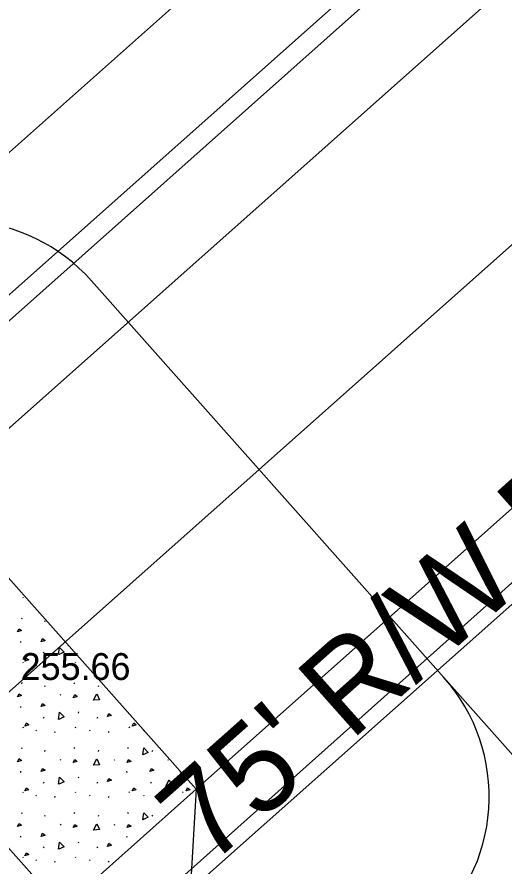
# Model space of a CAD drawing. Extents: x 49683 to 58852, y 49525 to 54803.
# Drawn here: x 53470 to 53524.4, y 51425.2 to 51520 of the extents above; entities that cross this region are included whole.
import ezdxf

# ---------------------------------------------------------------- set-up
doc = ezdxf.new("R2010")
doc.units = 0
for name, color, linetype in [('Level 1', 7, 'Continuous'), ('Level 11', 7, 'Continuous'), ('Level 13', 7, 'Continuous'), ('Level 15', 7, 'Continuous'), ('Level 18', 7, 'Continuous'), ('Level 19', 7, 'Continuous'), ('Level 25', 7, 'Continuous'), ('Level 3', 7, 'Continuous'), ('Level 32', 7, 'Continuous'), ('Level 5', 7, 'Continuous')]:
    doc.layers.add(name, color=color, linetype=linetype)

msp = doc.modelspace()

# ---------------------------------------------------------------- linework, layer by layer
at = {"layer": 'Level 1'}
msp.add_line((52544.807, 50683.302), (55534.583, 53340.862), dxfattribs=at)
at = {"layer": 'Level 11'}
msp.add_line((53245.856, 51207.553), (53944.235, 51830.768), dxfattribs=at)
at = {"layer": 'Level 13'}
msp.add_line((53681.554, 51593.39), (53435.601, 51374.767), dxfattribs=at)
at = {"layer": 'Level 15'}
for p, q in [((53460.734, 51466.679), (53909.18, 51865.296)), ((53938.412, 51832.41), (53489.966, 51433.793)), ((53460.734, 51466.679), (53489.966, 51433.793)), ((53470.608, 51455.238), (53470.663, 51455.155)), ((53475.017, 51420.506), (53445.785, 51453.392)), ((53470.503, 51452.824), (53470.558, 51452.949)), ((53473.071, 51452.505), (53473.127, 51452.63)), ((53470.351, 51450.286), (53470.365, 51450.161)), ((53472.933, 51448.98), (53472.988, 51449.105)), ((53470.608, 51447.996), (53470.663, 51447.912)), ((53472.084, 51447.643), (53472.14, 51447.559)), ((53474.195, 51447.371), (53474.251, 51447.496)), ((53476.465, 51447.996), (53476.521, 51447.912)), ((53470.503, 51445.581), (53470.558, 51445.706)), ((53476.36, 51445.581), (53476.415, 51445.706)), ((53473.071, 51445.262), (53473.127, 51445.387)), ((53479.071, 51445.262), (53479.127, 51445.387)), ((53474.806, 51444.374), (53474.861, 51444.291)), ((53470.351, 51443.043), (53470.365, 51442.918)), ((53472.933, 51441.738), (53472.988, 51441.863)), ((53476.824, 51442.307), (53476.879, 51442.432)), ((53478.933, 51441.738), (53478.988, 51441.863)), ((53470.608, 51440.753), (53470.663, 51440.67)), ((53476.465, 51440.753), (53476.521, 51440.67)), ((53482.465, 51440.753), (53482.521, 51440.67)), ((53472.084, 51440.4), (53472.14, 51440.317)), ((53474.195, 51440.128), (53474.251, 51440.253)), ((53478.084, 51440.4), (53478.14, 51440.317)), ((53480.195, 51440.128), (53480.251, 51440.253)), ((53484.084, 51440.4), (53484.14, 51440.317)), ((53470.503, 51438.339), (53470.558, 51438.464)), ((53473.071, 51438.02), (53473.127, 51438.144)), ((53476.36, 51438.339), (53476.415, 51438.464)), ((53479.071, 51438.02), (53479.127, 51438.144)), ((53482.36, 51438.339), (53482.415, 51438.464)), ((53485.071, 51438.02), (53485.127, 51438.144)), ((53474.806, 51437.132), (53474.861, 51437.048)), ((53480.806, 51437.132), (53480.861, 51437.048)), ((53486.806, 51437.132), (53486.861, 51437.048)), ((53470.351, 51435.8), (53470.365, 51435.676)), ((53476.824, 51435.064), (53476.879, 51435.189)), ((53482.209, 51435.8), (53482.223, 51435.676)), ((53488.213, 51435.766), (53488.223, 51435.676)), ((53472.933, 51434.495), (53472.988, 51434.62)), ((53478.933, 51434.495), (53478.988, 51434.62)), ((53484.933, 51434.495), (53484.988, 51434.62)), ((53470.608, 51433.51), (53470.663, 51433.427)), ((53472.084, 51433.157), (53472.14, 51433.074)), ((53489.966, 51433.793), (53475.017, 51420.506)), ((53476.465, 51433.51), (53476.521, 51433.427)), ((53478.084, 51433.157), (53478.14, 51433.074)), ((53482.465, 51433.51), (53482.521, 51433.427)), ((53484.084, 51433.157), (53484.14, 51433.074)), ((53488.465, 51433.51), (53488.521, 51433.427)), ((53489.966, 51433.793), (53489.143, 51419.818)), ((53474.195, 51432.886), (53474.251, 51433.011)), ((53480.195, 51432.886), (53480.251, 51433.011)), ((53486.195, 51432.886), (53486.251, 51433.011)), ((53470.503, 51431.096), (53470.558, 51431.221)), ((53473.071, 51430.777), (53473.127, 51430.902)), ((53476.36, 51431.096), (53476.415, 51431.221)), ((53479.071, 51430.777), (53479.127, 51430.902)), ((53482.36, 51431.096), (53482.415, 51431.221)), ((53485.071, 51430.777), (53485.127, 51430.902)), ((53474.806, 51429.889), (53474.861, 51429.806)), ((53480.806, 51429.889), (53480.861, 51429.806)), ((53470.351, 51428.558), (53470.365, 51428.433)), ((53482.209, 51428.558), (53482.223, 51428.433)), ((53476.824, 51427.821), (53476.879, 51427.946)), ((53472.933, 51427.253), (53472.988, 51427.378)), ((53478.933, 51427.253), (53478.988, 51427.378)), ((53470.608, 51426.268), (53470.663, 51426.185)), ((53472.084, 51425.915), (53472.14, 51425.831)), ((53474.195, 51425.643), (53474.251, 51425.768)), ((53476.465, 51426.268), (53476.521, 51426.185)), ((53478.084, 51425.915), (53478.14, 51425.831)), ((53480.195, 51425.643), (53480.251, 51425.768))]:
    msp.add_line(p, q, dxfattribs=at)
for points in [[(53470.036, 51451.362), (53470.202, 51451.709), (53470.48, 51451.501), (53470.036, 51451.362)], [(53472.658, 51450.264), (53472.824, 51450.611), (53473.102, 51450.403), (53472.658, 51450.264)], [(53474.621, 51448.837), (53474.731, 51449.63), (53475.228, 51449.117), (53474.634, 51448.842)], [(53470.851, 51448.092), (53471.018, 51448.439), (53471.295, 51448.231), (53470.851, 51448.092)], [(53470.036, 51444.119), (53470.202, 51444.466), (53470.48, 51444.258), (53470.036, 51444.119)], [(53476.263, 51444.013), (53476.429, 51444.36), (53476.707, 51444.152), (53476.263, 51444.013)], [(53478.52, 51443.724), (53478.894, 51444.431), (53479.186, 51443.779), (53478.534, 51443.724)], [(53472.658, 51443.022), (53472.824, 51443.368), (53473.102, 51443.16), (53472.658, 51443.022)], [(53474.621, 51441.594), (53474.731, 51442.387), (53475.228, 51441.874), (53474.634, 51441.599)], [(53480.076, 51441.908), (53480.242, 51442.255), (53480.52, 51442.047), (53480.076, 51441.908)], [(53470.851, 51440.85), (53471.018, 51441.197), (53471.295, 51440.989), (53470.851, 51440.85)], [(53482.851, 51440.85), (53483.018, 51441.197), (53483.295, 51440.989), (53482.851, 51440.85)], [(53484.031, 51437.632), (53484.141, 51438.425), (53484.638, 51437.912), (53484.044, 51437.637)], [(53470.036, 51436.877), (53470.202, 51437.224), (53470.48, 51437.015), (53470.036, 51436.877)], [(53476.263, 51436.771), (53476.429, 51437.118), (53476.707, 51436.91), (53476.263, 51436.771)], [(53478.52, 51436.481), (53478.894, 51437.189), (53479.186, 51436.536), (53478.534, 51436.481)], [(53482.263, 51436.771), (53482.429, 51437.118), (53482.707, 51436.91), (53482.263, 51436.771)], [(53472.658, 51435.779), (53472.824, 51436.126), (53473.102, 51435.918), (53472.658, 51435.779)], [(53484.816, 51435.779), (53484.983, 51436.126), (53485.26, 51435.918), (53484.816, 51435.779)], [(53474.621, 51434.352), (53474.731, 51435.145), (53475.228, 51434.632), (53474.634, 51434.356)], [(53480.076, 51434.665), (53480.242, 51435.012), (53480.52, 51434.804), (53480.076, 51434.665)], [(53486.581, 51434.153), (53486.956, 51434.861), (53487.247, 51434.209), (53486.595, 51434.153)], [(53470.851, 51433.607), (53471.018, 51433.954), (53471.295, 51433.746), (53470.851, 51433.607)], [(53482.851, 51433.607), (53483.018, 51433.954), (53483.295, 51433.746), (53482.851, 51433.607)], [(53488.851, 51433.607), (53489.018, 51433.954), (53489.295, 51433.746), (53488.851, 51433.607)], [(53484.031, 51430.389), (53484.141, 51431.182), (53484.638, 51430.669), (53484.044, 51430.394)], [(53470.036, 51429.634), (53470.202, 51429.981), (53470.48, 51429.773), (53470.036, 51429.634)], [(53476.263, 51429.528), (53476.429, 51429.875), (53476.707, 51429.667), (53476.263, 51429.528)], [(53478.52, 51429.238), (53478.894, 51429.946), (53479.186, 51429.294), (53478.534, 51429.238)], [(53482.263, 51429.528), (53482.429, 51429.875), (53482.707, 51429.667), (53482.263, 51429.528)], [(53472.658, 51428.536), (53472.824, 51428.883), (53473.102, 51428.675), (53472.658, 51428.536)], [(53474.621, 51427.109), (53474.731, 51427.902), (53475.228, 51427.389), (53474.634, 51427.114)], [(53480.076, 51427.423), (53480.242, 51427.77), (53480.52, 51427.561), (53480.076, 51427.423)], [(53470.851, 51426.365), (53471.018, 51426.711), (53471.295, 51426.503), (53470.851, 51426.365)]]:
    msp.add_lwpolyline(points, dxfattribs=at)
at = {"layer": 'Level 18'}
for p, q in [((53478.298, 51490.54), (53517.657, 51446.261)), ((53517.657, 51446.261), (53526.295, 51436.543))]:
    msp.add_line(p, q, dxfattribs=at)
for centre, start, end in [((53463.35, 51477.253), 41.63337, 129.78743), ((53502.709, 51432.974), 310.60591, 41.63337)]:
    msp.add_arc(centre, 20, start, end, dxfattribs=at)
at = {"layer": 'Level 19'}
msp.add_line((52714.154, 50773.623), (54181.768, 52078.16), dxfattribs=at)
at = {"layer": 'Level 3'}
msp.add_line((53449.718, 51471.806), (53898.742, 51870.567), dxfattribs=at)
at = {"layer": 'Level 5'}
msp.add_line((53900.074, 51869.402), (53451.19, 51470.163), dxfattribs=at)

# ---------------------------------------------------------------- texts
at = {"layer": 'Level 25'}
msp.add_text("75' R/W FILE # 408-B", height=10, rotation=41.63333, dxfattribs=at).set_placement((53491.415, 51425.048))
at = {"layer": 'Level 32'}
msp.add_text('255.66', height=3, dxfattribs=at).set_placement((53470.377, 51445.995))

doc.saveas('drawing.dxf')
